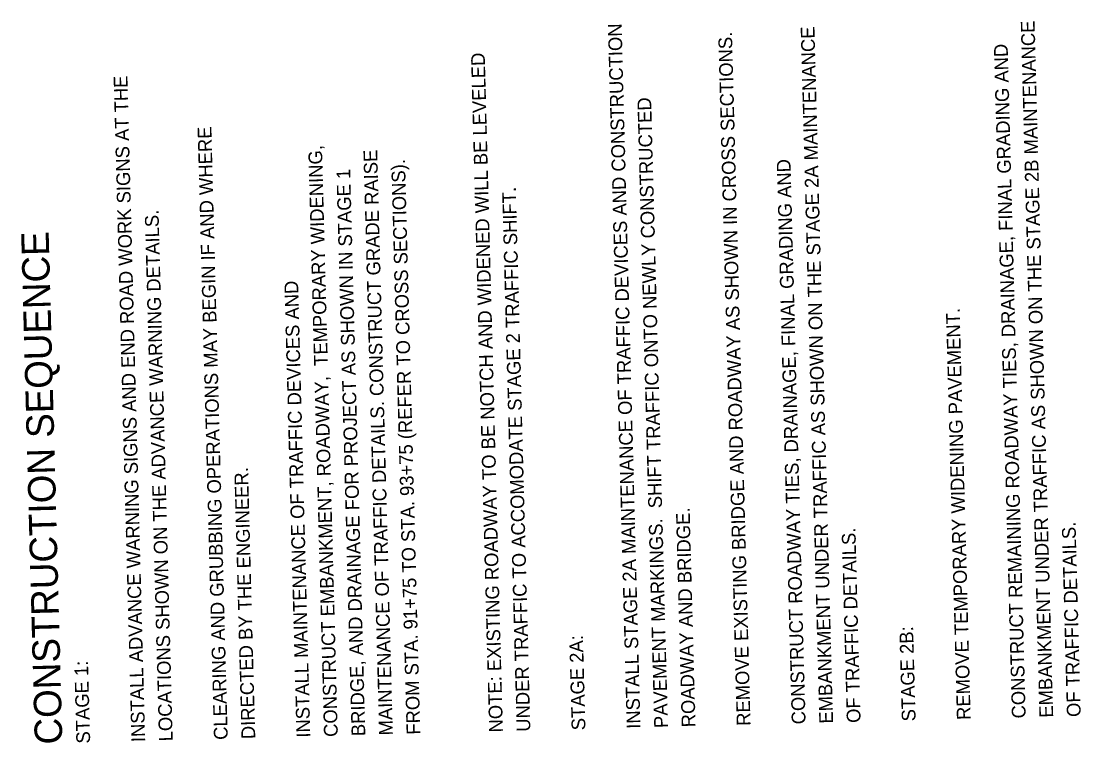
# Model space of a CAD drawing. Extents: x 1929653 to 1931621, y 596452 to 600944.
# Drawn here: x 1931158.8 to 1931620.8, y 597035.4 to 597350 of the extents above; entities that cross this region are included whole.
import ezdxf

# ---------------------------------------------------------------- set-up
doc = ezdxf.new("R2010")
doc.units = 0
doc.layers.add('R_Border', color=7, linetype='Continuous')

msp = doc.modelspace()

# ---------------------------------------------------------------- texts
at = {"layer": 'R_Border'}
for s, height, p in [('EMBANKMENT UNDER TRAFFIC AS SHOWN ON THE STAGE 2B MAINTENANCE', 6, (1931608.79, 597046.42)), ('INSTALL STAGE 2A MAINTENANCE OF TRAFFIC DEVICES AND CONSTRUCTION ', 6, (1931428.86, 597041.59)), ('EMBANKMENT UNDER TRAFFIC AS SHOWN ON THE STAGE 2A MAINTENANCE', 6, (1931512.83, 597043.84)), ('REMOVE EXISTING BRIDGE AND ROADWAY AS SHOWN IN CROSS SECTIONS.', 6, (1931476.84, 597042.87)), ('CONSTRUCT REMAINING ROADWAY TIES, DRAINAGE, FINAL GRADING AND', 6, (1931596.8, 597046.09)), ('NOTE: EXISTING ROADWAY TO BE NOTCH AND WIDENED WILL BE LEVELED ', 6, (1931368.88, 597039.98)), ('INSTALL ADVANCE WARNING SIGNS AND END ROAD WORK SIGNS AT THE', 6, (1931212.93, 597035.79)), ('PAVEMENT MARKINGS.  SHIFT TRAFFIC ONTO NEWLY CONSTRUCTED ', 6, (1931440.85, 597041.91)), ('CLEARING AND GRUBBING OPERATIONS MAY BEGIN IF AND WHERE', 6, (1931248.92, 597036.76)), ('CONSTRUCT EMBANKMENT, ROADWAY,  TEMPORARY WIDENING, ', 6, (1931296.9, 597038.04)), ('MAINTENANCE OF TRAFFIC DETAILS. CONSTRUCT GRADE RAISE ', 6, (1931320.9, 597038.69)), ('BRIDGE, AND DRAINAGE FOR PROJECT AS SHOWN IN STAGE 1  ', 6, (1931308.9, 597038.37)), ('FROM STA. 91+75 TO STA. 93+75 (REFER TO CROSS SECTIONS).', 6, (1931332.89, 597039.01)), ('CONSTRUCT ROADWAY TIES, DRAINAGE, FINAL GRADING AND', 6, (1931500.83, 597043.52)), ('UNDER TRAFFIC TO ACCOMODATE STAGE 2 TRAFFIC SHIFT.', 6, (1931380.87, 597040.3)), ('LOCATIONS SHOWN ON THE ADVANCE WARNING DETAILS.  ', 6, (1931224.93, 597036.11)), ('CONSTRUCTION SEQUENCE', 12, (1931176.82, 597034.82)), ('INSTALL MAINTENANCE OF TRAFFIC DEVICES AND ', 6, (1931284.91, 597037.72)), ('REMOVE TEMPORARY WIDENING PAVEMENT.', 6, (1931572.81, 597045.45)), ('DIRECTED BY THE ENGINEER.', 6, (1931260.92, 597037.08)), ('ROADWAY AND BRIDGE.', 6, (1931452.85, 597042.23)), ('OF TRAFFIC DETAILS.', 6, (1931524.82, 597044.16)), ('OF TRAFFIC DETAILS.', 6, (1931620.79, 597046.74)), ('STAGE 2B:', 6, (1931548.81, 597044.81)), ('STAGE 2A:', 6, (1931404.87, 597040.94)), ('STAGE 1:', 6, (1931188.94, 597035.15))]:
    msp.add_text(s, height=height, rotation=91.5377, dxfattribs=at).set_placement(p)

doc.saveas('drawing.dxf')
